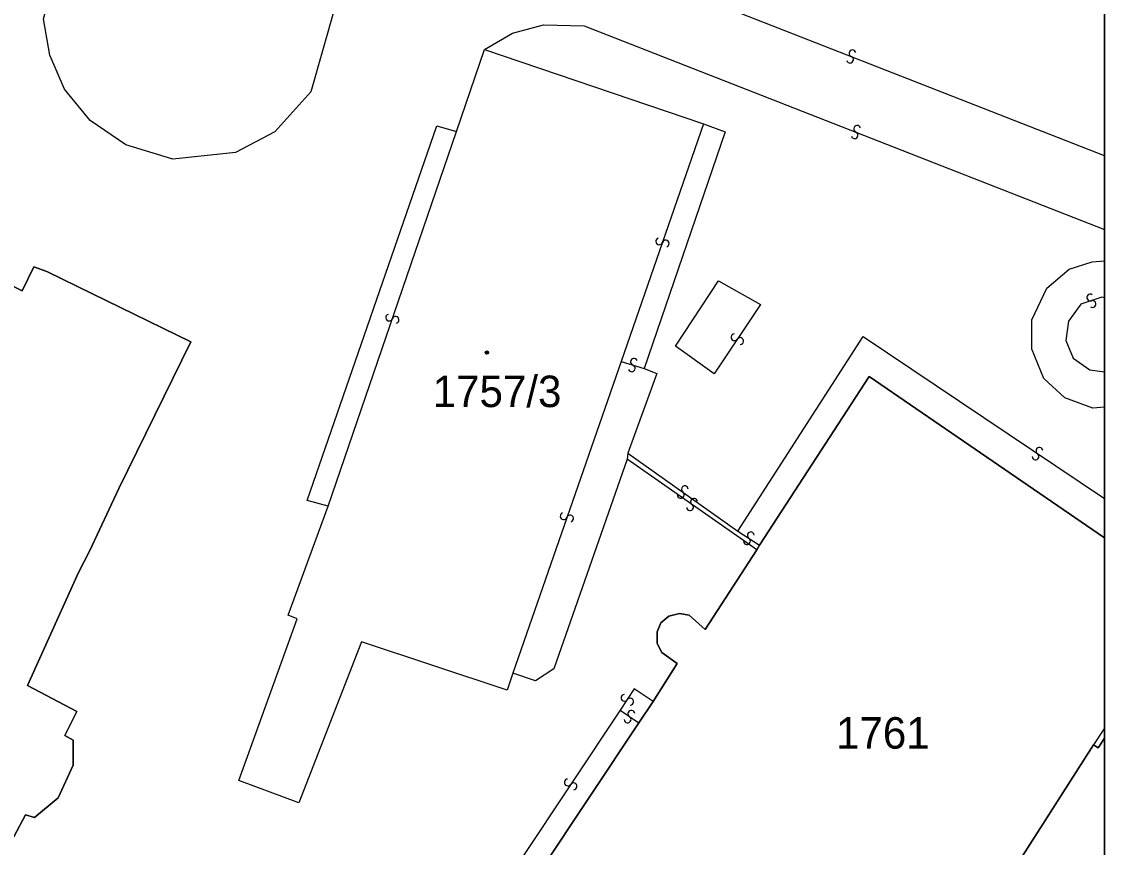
# Model space of a CAD drawing. Extents: x -600309 to -598967, y -1161267 to -1160292.
# Drawn here: x -599025.6 to -598967.1, y -1161158.2 to -1161113.7 of the extents above; entities that cross this region are included whole.
import ezdxf

# ---------------------------------------------------------------- set-up
doc = ezdxf.new("R2010")
doc.units = 0
for name, color, linetype in [('Level 1', 7, 'Continuous'), ('Level 13', 7, 'Continuous'), ('Level 3', 7, 'Continuous'), ('Level 4', 7, 'Continuous'), ('Level 5', 7, 'Continuous'), ('Level 60', 7, 'Continuous'), ('Vrstva 60', 7, 'Continuous'), ('Vrstva 63', 7, 'Continuous')]:
    doc.layers.add(name, color=color, linetype=linetype)

msp = doc.modelspace()

# ---------------------------------------------------------------- linework, layer by layer
at = {"layer": 'Level 1'}
for points in [[(-598995.61, -1161109.17), (-599006.75, -1161106.11), (-599009.98, -1161117.44), (-599011.92, -1161119.6), (-599014.04, -1161120.73), (-599017.42, -1161121.08), (-599019.96, -1161120.31), (-599021.9, -1161118.99), (-599023.29, -1161117.3), (-599024.08, -1161115.46), (-599024.41, -1161113.5), (-599021.06, -1161101.87), (-599024.92, -1161100.68), (-599023.19, -1161094.45), (-599024.67, -1161094.01)], [(-599002.11, -1161119.59), (-599000.6, -1161115.17)], [(-599000.6, -1161115.17), (-598988.76, -1161119.17)], [(-598988.76, -1161119.17), (-598987.59, -1161119.6), (-598991.96, -1161132.39)], [(-599009.03, -1161139.82), (-599010.18, -1161139.52), (-599003.16, -1161119.29), (-599002.11, -1161119.59)], [(-599026.01, -1161157.68), (-599025.38, -1161156.48), (-599024.9, -1161156.63), (-599023.62, -1161155.57), (-599022.81, -1161153.8), (-599022.81, -1161152.46), (-599023.27, -1161152.21), (-599022.62, -1161150.91), (-599025.28, -1161149.51), (-599022.53, -1161143.4), (-599021.91, -1161142.21), (-599020.34, -1161138.86), (-599016.46, -1161130.94), (-599021.76, -1161128.35), (-599024.24, -1161127.15), (-599024.94, -1161126.89), (-599025.57, -1161128.2), (-599031.8, -1161125.05)], [(-598991.96, -1161132.39), (-598991.29, -1161132.66), (-598992.85, -1161136.96)], [(-598967.108, -1161141.521), (-598979.81, -1161132.81), (-598985.73, -1161141.93)], [(-598992.88, -1161137.28), (-598996.84, -1161148.61), (-598997.83, -1161149.25), (-598999.06, -1161148.83)], [(-598992.85, -1161136.96), (-598992.88, -1161137.28)], [(-598999.06, -1161148.83), (-598999.37, -1161149.75), (-599007.24, -1161147.14), (-599010.62, -1161155.84), (-599013.87, -1161154.64), (-599010.71, -1161145.9), (-599011.19, -1161145.71), (-599009.03, -1161139.82)], [(-598985.88, -1161142.18), (-598985.73, -1161141.93)], [(-598991.49, -1161150.36), (-598990.19, -1161148.32), (-598991.01, -1161147.72), (-598991.27, -1161147.24), (-598991.27, -1161146.61), (-598991.06, -1161146.12), (-598990.63, -1161145.75), (-598990.06, -1161145.61), (-598989.53, -1161145.7), (-598988.68, -1161146.47), (-598985.88, -1161142.18)], [(-598991.49, -1161150.36), (-598992.26, -1161151.51)], [(-598997.59, -1161159.52), (-598992.26, -1161151.51)], [(-598967.108, -1161152.354), (-598967.45, -1161152.86), (-598967.69, -1161152.71)], [(-598967.69, -1161152.71), (-598974.29, -1161163.01)]]:
    msp.add_lwpolyline(points, dxfattribs=at)
at = {"layer": 'Level 13'}
for centre, start, end in [((-598980.849, -1161115.711), 195.98549, 68.08349), ((-598980.712, -1161115.369), 15.77104, 248.36104), ((-598980.598, -1161119.791), 195.77219, 68.36219), ((-598980.461, -1161119.449), 15.98665, 248.08465), ((-598991.154, -1161125.519), 108.02952, 340.61952), ((-598990.806, -1161125.642), 288.24397, 160.34197), ((-598967.869, -1161128.556), 56.19951, 288.78951), ((-598967.751, -1161128.905), 236.41396, 108.51196), ((-599005.744, -1161129.639), 108.48865, 340.58664), ((-599005.396, -1161129.76), 288.27419, 160.86419), ((-598987.093, -1161130.697), 93.39756, 325.98756), ((-598986.788, -1161130.904), 273.61202, 145.71001), ((-598992.523, -1161132.024), 20.04481, 252.14281), ((-598992.636, -1161132.375), 199.83036, 72.42036), ((-598970.616, -1161136.828), 3.50739, 235.60538), ((-598970.823, -1161137.132), 183.29293, 55.88293), ((-598989.987, -1161139.21), 181.87646, 54.46646), ((-598989.772, -1161138.91), 2.09092, 234.18892), ((-598989.274, -1161139.58), 2.16626, 234.75626), ((-598996.314, -1161140.359), 107.99116, 340.58116), ((-598995.966, -1161140.482), 288.20561, 160.30361), ((-598989.487, -1161139.88), 182.38071, 54.47871), ((-598986.208, -1161141.396), 4.36608, 236.46408), ((-598986.411, -1161141.704), 184.15163, 56.74163), ((-598993.032, -1161150.167), 93.35339, 325.94339), ((-598992.728, -1161150.374), 273.56784, 145.66584), ((-598992.862, -1161151.333), 183.59932, 56.18932), ((-598992.657, -1161151.027), 3.81378, 235.91178), ((-598996.093, -1161154.737), 93.48474, 326.07474), ((-598995.787, -1161154.944), 273.6992, 145.79719)]:
    msp.add_arc(centre, 0.184, start, end, dxfattribs=at)
at = {"layer": 'Level 3'}
msp.add_line((-598967.108, -1161151.797), (-598967.69, -1161152.71), dxfattribs=at)
for points in [[(-598967.108, -1161120.899), (-598995.73, -1161109.69), (-598995.61, -1161109.17)], [(-599000.6, -1161115.17), (-598999.08, -1161114.29), (-598997.4, -1161113.83), (-598995.2, -1161113.88), (-598967.108, -1161124.881)], [(-598988.76, -1161119.17), (-598993.21, -1161132)], [(-599009.03, -1161139.82), (-599002.11, -1161119.59)], [(-598967.108, -1161134.473), (-598967.73, -1161134.52), (-598969.24, -1161133.97), (-598970.37, -1161132.92), (-598971.02, -1161131.35), (-598971.02, -1161129.75), (-598970.22, -1161128.05), (-598969.01, -1161127.03), (-598967.76, -1161126.62), (-598967.108, -1161126.572)], [(-598987.95, -1161127.65), (-598985.69, -1161128.93), (-598988.19, -1161132.67), (-598990.27, -1161131.18), (-598987.95, -1161127.65)], [(-598967.108, -1161128.563), (-598967.25, -1161128.53), (-598968.38, -1161128.92), (-598969.05, -1161129.83), (-598969.19, -1161130.87), (-598968.79, -1161131.83), (-598967.9, -1161132.46), (-598967.108, -1161132.566)], [(-598986.9, -1161141.17), (-598980.13, -1161130.66), (-598967.108, -1161139.399)], [(-598993.21, -1161132), (-598999.06, -1161148.83)], [(-598993.21, -1161132), (-598991.96, -1161132.39)], [(-598985.88, -1161142.18), (-598992.88, -1161137.28)], [(-598992.85, -1161136.96), (-598986.9, -1161141.17)], [(-598986.9, -1161141.17), (-598985.73, -1161141.93)], [(-598991.49, -1161150.36), (-598992.5, -1161149.69), (-598993.27, -1161150.84)], [(-598993.27, -1161150.84), (-598998.6, -1161158.84)], [(-598993.27, -1161150.84), (-598992.26, -1161151.51)]]:
    msp.add_lwpolyline(points, dxfattribs=at)
at = {"layer": 'Level 5'}
for radius in [0.09, 0.0521]:
    msp.add_circle((-599000.46, -1161131.53), radius, dxfattribs=at)
at = {"layer": 'Level 60'}
for points in [[(-599006.75, -1161106.11), (-599009.98, -1161117.44), (-599011.92, -1161119.6), (-599014.04, -1161120.73), (-599017.42, -1161121.08), (-599019.96, -1161120.31), (-599021.9, -1161118.99), (-599023.29, -1161117.3), (-599024.08, -1161115.46), (-599024.41, -1161113.5)], [(-599031.8, -1161125.05), (-599025.57, -1161128.2), (-599024.94, -1161126.89), (-599024.24, -1161127.15), (-599021.76, -1161128.35), (-599016.46, -1161130.94), (-599020.34, -1161138.86), (-599021.91, -1161142.21), (-599022.53, -1161143.4), (-599025.28, -1161149.51), (-599022.62, -1161150.91), (-599023.27, -1161152.21), (-599022.81, -1161152.46), (-599022.81, -1161153.8), (-599023.62, -1161155.57), (-599024.9, -1161156.63), (-599025.38, -1161156.48), (-599026.01, -1161157.68)]]:
    msp.add_lwpolyline(points, dxfattribs=at)
msp.add_lwpolyline([(-599000.6, -1161115.17), (-598988.76, -1161119.17), (-598987.59, -1161119.6), (-598991.96, -1161132.39), (-598991.29, -1161132.66), (-598992.85, -1161136.96), (-598992.88, -1161137.28), (-598996.84, -1161148.61), (-598997.83, -1161149.25), (-598999.06, -1161148.83), (-598999.37, -1161149.75), (-599007.24, -1161147.14), (-599010.62, -1161155.84), (-599013.87, -1161154.64), (-599010.71, -1161145.9), (-599011.19, -1161145.71), (-599009.03, -1161139.82), (-599010.18, -1161139.52), (-599003.16, -1161119.29), (-599002.11, -1161119.59)], close=True, dxfattribs=at)
at = {"layer": 'Vrstva 60'}
for points in [[(-599006.75, -1161106.11), (-599009.98, -1161117.44), (-599011.92, -1161119.6), (-599014.04, -1161120.73), (-599017.42, -1161121.08), (-599019.96, -1161120.31), (-599021.9, -1161118.99), (-599023.29, -1161117.3), (-599024.08, -1161115.46), (-599024.41, -1161113.5)], [(-598997.59, -1161159.52), (-598992.26, -1161151.51), (-598991.49, -1161150.36), (-598990.19, -1161148.32), (-598991.01, -1161147.72), (-598991.27, -1161147.24), (-598991.27, -1161146.61), (-598991.06, -1161146.12), (-598990.63, -1161145.75), (-598990.06, -1161145.61), (-598989.53, -1161145.7), (-598988.68, -1161146.47), (-598985.88, -1161142.18), (-598985.73, -1161141.93), (-598979.81, -1161132.81), (-598967.108, -1161141.521), (-598967.108, -1161110.502)], [(-599031.8, -1161125.05), (-599025.57, -1161128.2), (-599024.94, -1161126.89), (-599024.24, -1161127.15), (-599021.76, -1161128.35), (-599016.46, -1161130.94), (-599020.34, -1161138.86), (-599021.91, -1161142.21), (-599022.53, -1161143.4), (-599025.28, -1161149.51), (-599022.62, -1161150.91), (-599023.27, -1161152.21), (-599022.81, -1161152.46), (-599022.81, -1161153.8), (-599023.62, -1161155.57), (-599024.9, -1161156.63), (-599025.38, -1161156.48), (-599026.01, -1161157.68)], [(-598974.29, -1161163.01), (-598967.69, -1161152.71), (-598967.45, -1161152.86), (-598967.108, -1161152.354), (-598967.108, -1161141.521), (-598979.81, -1161132.81), (-598985.73, -1161141.93), (-598985.88, -1161142.18), (-598988.68, -1161146.47), (-598989.53, -1161145.7), (-598990.06, -1161145.61), (-598990.63, -1161145.75), (-598991.06, -1161146.12), (-598991.27, -1161146.61), (-598991.27, -1161147.24), (-598991.01, -1161147.72), (-598990.19, -1161148.32), (-598991.49, -1161150.36), (-598992.26, -1161151.51), (-598997.59, -1161159.52)], [(-598967.108, -1161172.553), (-598967.108, -1161152.354), (-598967.45, -1161152.86), (-598967.69, -1161152.71), (-598974.29, -1161163.01)]]:
    msp.add_lwpolyline(points, dxfattribs=at)
msp.add_lwpolyline([(-598987.59, -1161119.6), (-598991.96, -1161132.39), (-598991.29, -1161132.66), (-598992.85, -1161136.96), (-598992.88, -1161137.28), (-598996.84, -1161148.61), (-598997.83, -1161149.25), (-598999.06, -1161148.83), (-598999.37, -1161149.75), (-599007.24, -1161147.14), (-599010.62, -1161155.84), (-599013.87, -1161154.64), (-599010.71, -1161145.9), (-599011.19, -1161145.71), (-599009.03, -1161139.82), (-599010.18, -1161139.52), (-599003.16, -1161119.29), (-599002.11, -1161119.59), (-599000.6, -1161115.17), (-598988.76, -1161119.17)], close=True, dxfattribs=at)
at = {"layer": 'Vrstva 63'}
msp.add_lwpolyline([(-600308.541, -1160292.347), (-598967.108, -1160292.347), (-598967.108, -1161267.031), (-600308.541, -1161267.031)], close=True, dxfattribs=at)

# ---------------------------------------------------------------- texts
at = {"layer": 'Level 4'}
for s, p in [('1757/3', (-599003.39, -1161134.47)), ('1761', (-598981.603, -1161152.91))]:
    msp.add_text(s, height=1.7, dxfattribs=at).set_placement(p)

doc.saveas('drawing.dxf')
